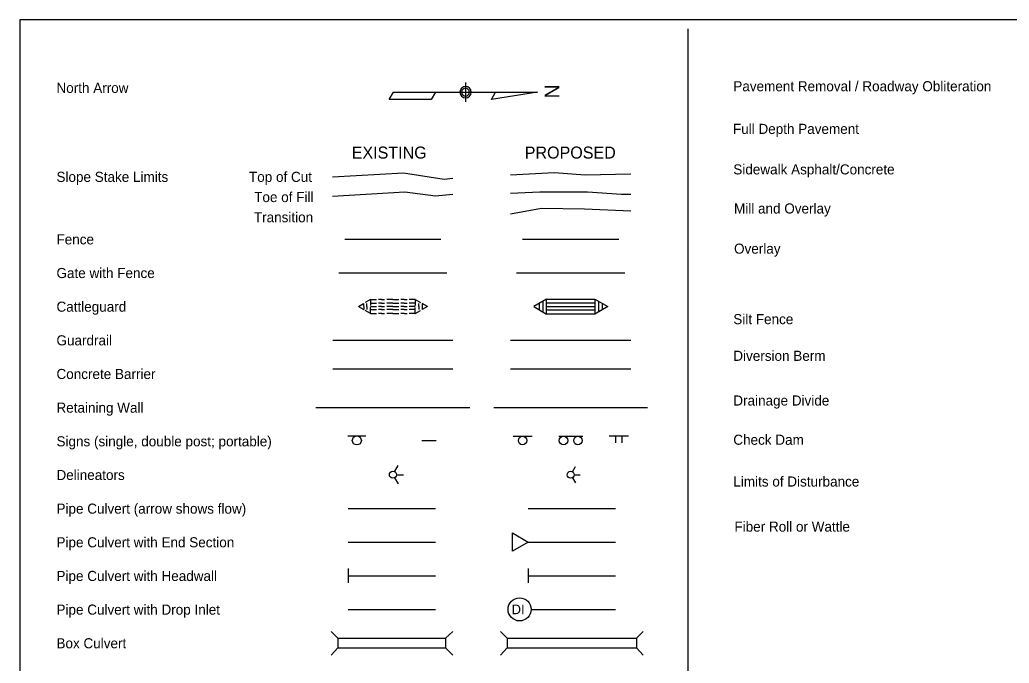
# Model space of a CAD drawing. Extents: x 0 to 2.72, y -0.06 to 0.86.
# Drawn here: x 1.425 to 2.111, y 0.419 to 0.865 of the extents above; entities that cross this region are included whole.
import ezdxf

# ---------------------------------------------------------------- set-up
doc = ezdxf.new("R2010")
doc.units = 0
for name, color, linetype in [('D_Details', 7, 'Continuous'), ('D_Dimensions', 7, 'Continuous'), ('Default', 7, 'Continuous'), ('E_GEO_Toe_of_Slope', 7, 'Continuous'), ('E_GEO_Top_of_Bank', 7, 'Continuous'), ('E_HYD_Culvert', 7, 'Continuous'), ('E_MAP_Non_DTM_Point', 7, 'Continuous'), ('E_PLM_Barrier', 7, 'Continuous'), ('E_PLM_Cattle_Guard', 7, 'Continuous'), ('E_PLM_Fence', 7, 'Continuous'), ('E_PLM_Gate', 7, 'Continuous'), ('E_PLM_Guardrail', 7, 'Continuous'), ('E_PLM_Headwall', 7, 'Continuous'), ('E_PLM_Misc_Features', 7, 'Continuous'), ('E_PLM_Signs', 7, 'Continuous'), ('E_PLM_Walls', 7, 'Continuous'), ('P_HYD_Inlets', 7, 'Continuous'), ('P_HYD_Pipe_Culvert', 7, 'Continuous'), ('P_HYD_Pipe_End_Section', 7, 'Continuous'), ('P_HYD_Pipe_Headwall', 7, 'Continuous'), ('P_RDW_Fencing', 7, 'Continuous'), ('P_RDW_Gate', 7, 'Continuous'), ('P_RDW_Guardrail_Systems', 7, 'Continuous'), ('P_RDW_Slope_Stake_Limits', 7, 'Continuous'), ('P_RDW_Walls', 7, 'Continuous'), ('P_STR_Cattle_Guard', 7, 'Continuous'), ('P_STR_Concrete_Barrier', 7, 'Continuous'), ('P_TC_Delineators', 7, 'Continuous'), ('P_TC_Signs_Permanent', 7, 'Continuous'), ('P_TC_Signs_Temporary', 7, 'Continuous')]:
    doc.layers.add(name, color=color, linetype=linetype)

msp = doc.modelspace()

# ---------------------------------------------------------------- linework, layer by layer
at = {"layer": 'D_Details'}
for p, q in [((1.88821, 0.85833), (1.88821, 0.08127)), ((1.734, 0.82111), (1.734, 0.80778)), ((1.71316, 0.81445), (1.75483, 0.81445)), ((1.7301, 0.81445), (1.73126, 0.81445)), ((1.7379, 0.81445), (1.73673, 0.81445))]:
    msp.add_line(p, q, dxfattribs=at)
for points in [[(1.684, 0.81445), (1.71316, 0.81445), (1.71025, 0.80945), (1.68108, 0.80945)], [(1.784, 0.81445), (1.75191, 0.80945), (1.75483, 0.81445)]]:
    msp.add_lwpolyline(points, close=True, dxfattribs=at)
for radius, start, end in [(0.0039, 90, 180), (0.00273, 90, 180), (0.0039, 360, 90), (0.00273, 360, 90), (0.0039, 180, 270), (0.00273, 180, 270), (0.0039, 270, 0), (0.00273, 270, 0)]:
    msp.add_arc((1.734, 0.81445), radius, start, end, dxfattribs=at)
at = {"layer": 'Default'}
msp.add_lwpolyline([(1.42482, -0.00206), (2.72482, -0.00206), (2.72482, 0.86461), (1.42482, 0.86461)], close=True, dxfattribs=at)
at = {"layer": 'E_GEO_Toe_of_Slope'}
msp.add_lwpolyline([(1.64176, 0.74232), (1.69189, 0.74544), (1.71317, 0.74246), (1.72509, 0.74363)], dxfattribs=at)
at = {"layer": 'E_GEO_Top_of_Bank'}
msp.add_lwpolyline([(1.64176, 0.75566), (1.691, 0.7586), (1.7191, 0.7541), (1.72509, 0.75491)], dxfattribs=at)
at = {"layer": 'E_HYD_Culvert'}
for p, q in [((1.65248, 0.5259), (1.71305, 0.5259)), ((1.65248, 0.50257), (1.71305, 0.50257)), ((1.65248, 0.47923), (1.71305, 0.47923)), ((1.65248, 0.4559), (1.71305, 0.4559)), ((1.64541, 0.4359), (1.72012, 0.4359)), ((1.64541, 0.42923), (1.72012, 0.42923))]:
    msp.add_line(p, q, dxfattribs=at)
for points in [[(1.64075, 0.44057), (1.64541, 0.4359), (1.64541, 0.42923), (1.64075, 0.42422)], [(1.72512, 0.44057), (1.72012, 0.4359), (1.72012, 0.42923), (1.72512, 0.42422)]]:
    msp.add_lwpolyline(points, dxfattribs=at)
at = {"layer": 'E_MAP_Non_DTM_Point'}
for p, q in [((1.68372, 0.66586), (1.68372, 0.66586)), ((1.6586, 0.57298), (1.6586, 0.57298)), ((1.6836, 0.54923), (1.6836, 0.54923))]:
    msp.add_line(p, q, dxfattribs=at)
at = {"layer": 'E_PLM_Barrier'}
msp.add_line((1.64193, 0.62257), (1.72527, 0.62257), dxfattribs=at)
at = {"layer": 'E_PLM_Cattle_Guard'}
for p, q in [((1.65974, 0.66589), (1.66334, 0.66799)), ((1.65974, 0.66589), (1.66335, 0.6638)), ((1.66334, 0.66799), (1.66335, 0.6638)), ((1.66807, 0.67074), (1.66447, 0.66864)), ((1.66564, 0.66589), (1.66564, 0.66797)), ((1.66564, 0.66589), (1.66564, 0.6638)), ((1.66807, 0.67074), (1.67223, 0.67074)), ((1.66807, 0.67074), (1.66807, 0.66657)), ((1.66807, 0.66821), (1.67223, 0.66821)), ((1.66807, 0.6659), (1.67223, 0.6659)), ((1.67582, 0.67074), (1.67373, 0.67074)), ((1.67582, 0.66821), (1.67373, 0.66821)), ((1.67582, 0.6659), (1.67373, 0.6659)), ((1.67582, 0.67074), (1.6779, 0.67074)), ((1.67582, 0.66821), (1.6779, 0.66821)), ((1.67582, 0.66589), (1.6779, 0.66589)), ((1.68357, 0.67074), (1.6794, 0.67074)), ((1.68357, 0.66821), (1.6794, 0.66821)), ((1.68357, 0.66589), (1.6794, 0.66589)), ((1.68357, 0.67074), (1.68773, 0.67074)), ((1.68357, 0.66821), (1.68773, 0.66821)), ((1.68357, 0.66589), (1.68773, 0.66589)), ((1.69132, 0.67074), (1.68923, 0.67074)), ((1.69132, 0.66821), (1.68923, 0.66821)), ((1.69132, 0.6659), (1.68923, 0.6659)), ((1.69132, 0.67074), (1.6934, 0.67074)), ((1.69132, 0.66821), (1.6934, 0.66821)), ((1.69132, 0.6659), (1.6934, 0.6659)), ((1.69907, 0.67074), (1.6949, 0.67074)), ((1.69907, 0.66821), (1.6949, 0.66821)), ((1.69907, 0.6659), (1.6949, 0.6659)), ((1.69907, 0.67074), (1.70268, 0.66866)), ((1.69907, 0.67074), (1.69907, 0.66657)), ((1.70162, 0.66591), (1.70162, 0.668)), ((1.70162, 0.66591), (1.70162, 0.66383)), ((1.70752, 0.66589), (1.7039, 0.66796)), ((1.70752, 0.66589), (1.7039, 0.66382)), ((1.70392, 0.66794), (1.70392, 0.66384)), ((1.70392, 0.66794), (1.70392, 0.66384)), ((1.66807, 0.66106), (1.66446, 0.66315)), ((1.66807, 0.66106), (1.66807, 0.66523)), ((1.66807, 0.66376), (1.67223, 0.66376)), ((1.66807, 0.66106), (1.67223, 0.66106)), ((1.67582, 0.66376), (1.67373, 0.66376)), ((1.67582, 0.66106), (1.67373, 0.66106)), ((1.67582, 0.66376), (1.6779, 0.66376)), ((1.67582, 0.66106), (1.6779, 0.66106)), ((1.68357, 0.66376), (1.6794, 0.66376)), ((1.68357, 0.66106), (1.6794, 0.66106)), ((1.68357, 0.66376), (1.68773, 0.66376)), ((1.68357, 0.66106), (1.68773, 0.66106)), ((1.69132, 0.66376), (1.68923, 0.66376)), ((1.69132, 0.66106), (1.68923, 0.66106)), ((1.69132, 0.66376), (1.6934, 0.66376)), ((1.69132, 0.66106), (1.6934, 0.66106)), ((1.69907, 0.66376), (1.6949, 0.66376)), ((1.69907, 0.66106), (1.6949, 0.66106)), ((1.69907, 0.66106), (1.69907, 0.66523)), ((1.69907, 0.66106), (1.70269, 0.66313))]:
    msp.add_line(p, q, dxfattribs=at)
at = {"layer": 'E_PLM_Fence'}
for p, q in [((1.65027, 0.71257), (1.71693, 0.71257)), ((1.6461, 0.68923), (1.6711, 0.68923)), ((1.6961, 0.68923), (1.7211, 0.68923))]:
    msp.add_line(p, q, dxfattribs=at)
at = {"layer": 'E_PLM_Gate'}
msp.add_line((1.6711, 0.68923), (1.6961, 0.68923), dxfattribs=at)
at = {"layer": 'E_PLM_Guardrail'}
msp.add_line((1.64193, 0.64257), (1.72527, 0.64257), dxfattribs=at)
at = {"layer": 'E_PLM_Headwall'}
msp.add_line((1.65248, 0.48423), (1.65248, 0.47423), dxfattribs=at)
at = {"layer": 'E_PLM_Misc_Features'}
for p, q in [((1.68481, 0.55132), (1.68723, 0.55553)), ((1.68602, 0.54923), (1.69086, 0.54923)), ((1.68481, 0.54715), (1.68723, 0.54294))]:
    msp.add_line(p, q, dxfattribs=at)
msp.add_circle((1.6836, 0.54923), 0.00242, dxfattribs=at)
at = {"layer": 'E_PLM_Signs'}
msp.add_line((1.7036, 0.57298), (1.7136, 0.57298), dxfattribs=at)
msp.add_lwpolyline([(1.65235, 0.57611), (1.66485, 0.57611)], dxfattribs=at)
msp.add_circle((1.6586, 0.57298), 0.00313, dxfattribs=at)
at = {"layer": 'E_PLM_Walls'}
msp.add_line((1.63027, 0.5959), (1.73693, 0.5959), dxfattribs=at)
at = {"layer": 'P_HYD_Inlets'}
msp.add_circle((1.77148, 0.4559), 0.008, dxfattribs=at)
at = {"layer": 'P_HYD_Pipe_Culvert'}
for p, q in [((1.77748, 0.5259), (1.83805, 0.5259)), ((1.77748, 0.50257), (1.83805, 0.50257)), ((1.77748, 0.47923), (1.83805, 0.47923)), ((1.77948, 0.4559), (1.83805, 0.4559)), ((1.76291, 0.4359), (1.85262, 0.4359)), ((1.76291, 0.42923), (1.85262, 0.42923))]:
    msp.add_line(p, q, dxfattribs=at)
for points in [[(1.75825, 0.44057), (1.76291, 0.4359), (1.76291, 0.42923), (1.75825, 0.42423)], [(1.85729, 0.44057), (1.85262, 0.4359), (1.85262, 0.42923), (1.85729, 0.42423)]]:
    msp.add_lwpolyline(points, dxfattribs=at)
at = {"layer": 'P_HYD_Pipe_End_Section'}
msp.add_lwpolyline([(1.77748, 0.50257), (1.76648, 0.49623), (1.76648, 0.5089)], close=True, dxfattribs=at)
at = {"layer": 'P_HYD_Pipe_Headwall'}
msp.add_line((1.77748, 0.48423), (1.77748, 0.47423), dxfattribs=at)
at = {"layer": 'P_RDW_Fencing'}
for p, q in [((1.7736, 0.71257), (1.84027, 0.71257)), ((1.76943, 0.68923), (1.79443, 0.68923)), ((1.81943, 0.68923), (1.84443, 0.68923))]:
    msp.add_line(p, q, dxfattribs=at)
at = {"layer": 'P_RDW_Gate'}
msp.add_line((1.79443, 0.68923), (1.81943, 0.68923), dxfattribs=at)
at = {"layer": 'P_RDW_Guardrail_Systems'}
msp.add_line((1.76527, 0.64257), (1.8486, 0.64257), dxfattribs=at)
at = {"layer": 'P_RDW_Slope_Stake_Limits'}
for points in [[(1.76525, 0.75718), (1.79558, 0.75877), (1.81707, 0.75721), (1.84858, 0.75782)], [(1.76525, 0.74452), (1.78556, 0.74544), (1.8185, 0.74544), (1.84214, 0.74371), (1.84858, 0.7438)], [(1.76525, 0.73008), (1.78678, 0.73398), (1.81659, 0.73356), (1.84858, 0.73223)]]:
    msp.add_lwpolyline(points, dxfattribs=at)
at = {"layer": 'P_RDW_Walls'}
msp.add_line((1.7536, 0.5959), (1.86027, 0.5959), dxfattribs=at)
at = {"layer": 'P_STR_Cattle_Guard'}
for p, q in [((1.78506, 0.66798), (1.78506, 0.66361)), ((1.78765, 0.66946), (1.78765, 0.66211)), ((1.79027, 0.66829), (1.8236, 0.66829)), ((1.79027, 0.6659), (1.8236, 0.6659)), ((1.82632, 0.66946), (1.82632, 0.66216)), ((1.82881, 0.66798), (1.82881, 0.66358)), ((1.79027, 0.66351), (1.8236, 0.66351))]:
    msp.add_line(p, q, dxfattribs=at)
for points in [[(1.79027, 0.67101), (1.7813, 0.6658), (1.79027, 0.66059)], [(1.8236, 0.67101), (1.83267, 0.6658), (1.8236, 0.66059)]]:
    msp.add_lwpolyline(points, dxfattribs=at)
msp.add_lwpolyline([(1.79027, 0.67101), (1.8236, 0.67101), (1.8236, 0.66059), (1.79027, 0.66059)], close=True, dxfattribs=at)
at = {"layer": 'P_STR_Concrete_Barrier'}
msp.add_line((1.76527, 0.62257), (1.8486, 0.62257), dxfattribs=at)
at = {"layer": 'P_TC_Delineators'}
for p, q in [((1.80815, 0.55132), (1.81023, 0.55493)), ((1.80935, 0.54923), (1.81352, 0.54923)), ((1.80814, 0.54714), (1.81023, 0.54353))]:
    msp.add_line(p, q, dxfattribs=at)
msp.add_circle((1.80693, 0.54923), 0.00242, dxfattribs=at)
at = {"layer": 'P_TC_Signs_Permanent'}
msp.add_line((1.7986, 0.5759), (1.81527, 0.5759), dxfattribs=at)
msp.add_lwpolyline([(1.76693, 0.5759), (1.7736, 0.5759), (1.78027, 0.5759)], dxfattribs=at)
for centre in [(1.7736, 0.57298), (1.80193, 0.57298), (1.81193, 0.57298)]:
    msp.add_circle(centre, 0.00292, dxfattribs=at)
at = {"layer": 'P_TC_Signs_Temporary'}
for p, q in [((1.84693, 0.5759), (1.8336, 0.5759)), ((1.83805, 0.5759), (1.83805, 0.57145)), ((1.84249, 0.5759), (1.84249, 0.57145))]:
    msp.add_line(p, q, dxfattribs=at)

# ---------------------------------------------------------------- texts
at = {"layer": 'D_Details'}
msp.add_text('N', height=0.01, rotation=270, dxfattribs=at).set_placement((1.789, 0.81978))
at = {"layer": 'D_Dimensions'}
for s, height, p in [('North Arrow', 0.007, (1.45027, 0.81391)), ('Pavement Removal / Roadway Obliteration', 0.007, (1.91974, 0.81506)), ('Full Depth Pavement', 0.007, (1.9195, 0.78549)), ('EXISTING', 0.008333, (1.65505, 0.7684)), ('PROPOSED', 0.008333, (1.77506, 0.7684)), ('Sidewalk Asphalt/Concrete', 0.007, (1.91975, 0.75742)), ('Slope Stake Limits', 0.007, (1.45027, 0.75223)), ('Top of Cut', 0.007, (1.58379, 0.75223)), ('Toe of Fill', 0.007, (1.58741, 0.73823)), ('Mill and Overlay', 0.007, (1.92024, 0.73032)), ('Transition', 0.007, (1.58721, 0.72423)), ('Fence', 0.007, (1.45027, 0.7089)), ('Overlay', 0.007, (1.92025, 0.70246)), ('Gate with Fence', 0.007, (1.45027, 0.68557)), ('Cattleguard', 0.007, (1.45027, 0.66223)), ('Silt Fence', 0.007, (1.91974, 0.6536)), ('Guardrail', 0.007, (1.45027, 0.6389)), ('Diversion Berm', 0.007, (1.91974, 0.62818)), ('Concrete Barrier', 0.007, (1.45027, 0.61557)), ('Drainage Divide', 0.007, (1.91974, 0.59719)), ('Retaining Wall', 0.007, (1.45027, 0.59223)), ('Check Dam', 0.007, (1.91974, 0.56999)), ('Signs (single, double post; portable)', 0.007, (1.45027, 0.5689)), ('Delineators', 0.007, (1.45027, 0.54557)), ('Limits of Disturbance', 0.007, (1.91974, 0.54102)), ('Pipe Culvert (arrow shows flow)', 0.007, (1.45027, 0.52223)), ('Fiber Roll or Wattle', 0.007, (1.92053, 0.50976)), ('Pipe Culvert with End Section', 0.007, (1.45027, 0.4989)), ('Pipe Culvert with Headwall', 0.007, (1.45027, 0.47557)), ('Pipe Culvert with Drop Inlet', 0.007, (1.45027, 0.45223)), ('Box Culvert', 0.007, (1.45027, 0.4289))]:
    msp.add_text(s, height=height, dxfattribs=at).set_placement(p)
at = {"layer": 'P_HYD_Inlets'}
msp.add_text('DI', height=0.006667, dxfattribs=at).set_placement((1.76602, 0.45257))

doc.saveas('drawing.dxf')
